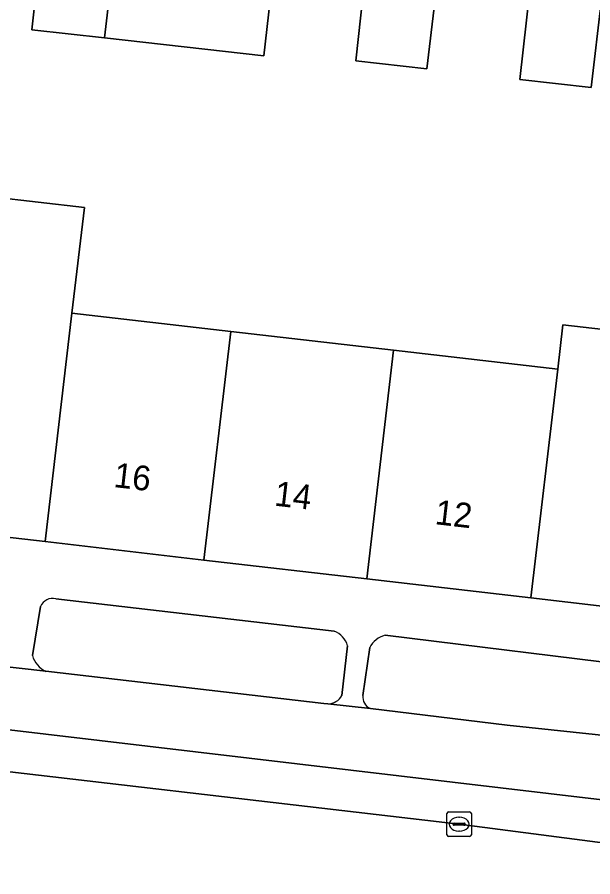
# Model space of a CAD drawing. Extents: x 161692 to 162379, y 380760 to 381678.
# Drawn here: x 162199.65 to 162222.97, y 380911.13 to 380945.92 of the extents above; entities that cross this region are included whole.
import ezdxf

# ---------------------------------------------------------------- set-up
doc = ezdxf.new("R2010")
doc.units = 0
for name, color, linetype in [('IMGEO_Erf', 7, 'Continuous'), ('IMGEO_Groenvoorziening', 7, 'Continuous'), ('IMGEO_Kolk', 7, 'Continuous'), ('IMGEO_Pand', 7, 'Continuous'), ('IMGEO_Pand_nummerreeks', 7, 'Continuous'), ('IMGEO_Parkeervlak_open', 7, 'Continuous'), ('IMGEO_Rijbaan_lokaal_open', 7, 'Continuous'), ('IMGEO_Voetpad_open', 7, 'Continuous')]:
    doc.layers.add(name, color=color, linetype=linetype)

msp = doc.modelspace()

# ---------------------------------------------------------------- linework, layer by layer
at = {"layer": 'IMGEO_Erf'}
for points in [[(162210.092, 380948.286), (162209.651, 380944.358), (162203.188, 380945.084), (162200.242, 380945.415), (162200.683, 380949.343)], [(162216.679, 380947.468), (162216.249, 380943.827), (162213.366, 380944.151), (162213.784, 380947.871)], [(162223.324, 380946.659), (162222.904, 380943.079), (162220.018, 380943.404), (162220.423, 380947.012)], [(162196.729, 380938.872), (162202.378, 380938.225), (162201.872, 380933.936), (162208.311, 380933.198), (162214.905, 380932.442), (162221.551, 380931.68), (162221.756, 380933.47), (162227.997, 380932.755)]]:
    msp.add_lwpolyline(points, dxfattribs=at)
at = {"layer": 'IMGEO_Groenvoorziening'}
for points in [[(162212.489, 380921.068), (162201.22, 380922.384)], [(162200.594, 380922.067), (162200.275, 380920.087)], [(162225.298, 380919.583), (162214.556, 380920.903)], [(162212.812, 380918.469), (162213.037, 380920.478)], [(162213.937, 380920.406), (162213.662, 380918.467)], [(162200.813, 380919.445), (162212.072, 380918.141), (162212.234, 380918.123)], [(162213.961, 380917.936), (162219.5, 380917.26), (162224.855, 380916.697)]]:
    msp.add_lwpolyline(points, dxfattribs=at)
for centre, radius, start, end in [((162201.099, 380921.846), 0.551, 77.3137, 156.4007), ((162212.213, 380920.262), 0.852, 14.6737, 71.099), ((162214.778, 380919.992), 0.938, 103.7154, 153.8071), ((162201.203, 380920.318), 0.957, 194.0021, 245.9243), ((162212.223, 380918.797), 0.674, 270.9057, 330.9051), ((162214.151, 380918.393), 0.495, 171.3558, 247.4109)]:
    msp.add_arc(centre, radius, start, end, dxfattribs=at)
at = {"layer": 'IMGEO_Kolk'}
for p, q in [((162217.132, 380913.757), (162217.984, 380913.757)), ((162217.057, 380912.831), (162217.057, 380913.683)), ((162217.545, 380913.537), (162217.57, 380913.537)), ((162218.058, 380913.683), (162218.058, 380912.831)), ((162217.316, 380913.251), (162217.316, 380913.263)), ((162217.754, 380913.214), (162217.356, 380913.214)), ((162217.359, 380913.3), (162217.757, 380913.3)), ((162217.8, 380913.263), (162217.8, 380913.251)), ((162217.984, 380912.757), (162217.132, 380912.757)), ((162217.568, 380912.977), (162217.543, 380912.977))]:
    msp.add_line(p, q, dxfattribs=at)
for points in [[(162217.132, 380913.757), (162217.984, 380913.757)], [(162217.057, 380912.831), (162217.057, 380913.683)], [(162218.058, 380913.683), (162218.058, 380912.831)], [(162217.984, 380912.757), (162217.132, 380912.757)]]:
    msp.add_lwpolyline(points, dxfattribs=at)
for centre, radius, start, end in [((162217.134, 380913.681), 0.0765, 91.552, 178.448), ((162217.134, 380913.681), 0.0765, 91.552, 178.448), ((162217.982, 380913.681), 0.0765, 1.552, 88.448), ((162217.982, 380913.681), 0.0765, 1.552, 88.448), ((162217.356, 380913.26), 0.0403, 85.8775, 175.7526), ((162217.353, 380913.25), 0.0366, 178.938, 274.7102), ((162217.757, 380913.257), 0.043, 264.8664, 352.4533), ((162217.761, 380913.262), 0.0386, 1.7309, 96.639), ((162217.134, 380912.833), 0.0765, 181.552, 268.448), ((162217.134, 380912.833), 0.0765, 181.552, 268.448), ((162217.982, 380912.833), 0.0765, 271.552, 358.448), ((162217.982, 380912.833), 0.0765, 271.552, 358.448)]:
    msp.add_arc(centre, radius, start, end, dxfattribs=at)
for centre, major_axis, ratio, start_param, end_param in [((162217.544, 380913.257), (-0.387, 0.002), 0.722429, 4.712389, 7.853982), ((162217.569, 380913.257), (-0.39, 0.002), 0.717154, 1.570796, 4.712389)]:
    msp.add_ellipse(centre, major_axis=major_axis, ratio=ratio, start_param=start_param, end_param=end_param, dxfattribs=at)
at = {"layer": 'IMGEO_Pand'}
for points in [[(162203.188, 380945.084), (162203.651, 380949.01), (162200.683, 380949.343), (162200.242, 380945.415)], [(162203.188, 380945.084), (162209.651, 380944.358), (162210.092, 380948.286), (162203.651, 380949.01)], [(162216.679, 380947.468), (162216.688, 380947.545), (162213.784, 380947.871), (162213.366, 380944.151), (162216.249, 380943.827)], [(162223.324, 380946.659), (162223.34, 380946.798), (162220.436, 380947.124), (162220.423, 380947.012), (162220.018, 380943.404), (162222.904, 380943.079)], [(162201.872, 380933.936), (162202.378, 380938.225), (162196.729, 380938.872), (162195.906, 380938.966), (162195.532, 380939.009), (162195.488, 380938.633), (162195.419, 380938.052), (162195.026, 380934.72), (162193.937, 380925.486), (162200.781, 380924.694)], [(162201.872, 380933.936), (162200.781, 380924.694), (162207.219, 380923.949), (162208.311, 380933.198)], [(162227.997, 380932.755), (162221.756, 380933.47), (162221.551, 380931.68), (162220.458, 380922.418), (162226.693, 380921.696)], [(162213.812, 380923.186), (162214.905, 380932.442), (162208.311, 380933.198), (162207.219, 380923.949)], [(162220.458, 380922.418), (162221.551, 380931.68), (162214.905, 380932.442), (162213.812, 380923.186)]]:
    msp.add_lwpolyline(points, close=True, dxfattribs=at)
at = {"layer": 'IMGEO_Parkeervlak_open'}
for points in [[(162247.804, 380913.155), (162247.621, 380914.14), (162246.189, 380913.913), (162242.624, 380913.349), (162241.292, 380913.209), (162238.109, 380913.042), (162236.135, 380912.951), (162233.539, 380913.036), (162176.321, 380919.783)], [(162175.911, 380918.063), (162194.36, 380915.961), (162217.557, 380913.256), (162231.163, 380911.496), (162234.33, 380911.127)]]:
    msp.add_lwpolyline(points, dxfattribs=at)
at = {"layer": 'IMGEO_Rijbaan_lokaal_open'}
msp.add_lwpolyline([(162234.33, 380911.127), (162231.163, 380911.496), (162217.557, 380913.256), (162194.36, 380915.961)], dxfattribs=at)
at = {"layer": 'IMGEO_Voetpad_open'}
for points in [[(162246.079, 380919.46), (162239.67, 380920.198), (162233.283, 380920.934), (162232.951, 380920.972), (162226.693, 380921.696), (162220.458, 380922.418), (162213.812, 380923.186), (162207.219, 380923.949), (162200.781, 380924.694), (162193.937, 380925.486), (162187.797, 380926.197), (162180.993, 380926.984), (162174.757, 380927.705), (162168.21, 380928.463), (162168.105, 380928.475), (162161.646, 380929.214), (162155.105, 380929.962), (162148.655, 380930.7), (162144.778, 380931.153)], [(162200.813, 380919.445), (162198.762, 380919.679), (162187.648, 380920.991), (162185.902, 380921.167), (162185.669, 380921.214), (162174.637, 380922.44), (162172.806, 380922.582), (162172.549, 380922.602), (162160.992, 380923.909), (162159.272, 380924.264), (162153.979, 380924.897), (162153.157, 380924.996), (162141.863, 380926.228), (162138.143, 380926.533), (162138.047, 380925.435)], [(162201.22, 380922.384), (162212.489, 380921.068)], [(162200.275, 380920.087), (162200.594, 380922.067)], [(162214.556, 380920.903), (162225.298, 380919.583)], [(162213.037, 380920.478), (162212.812, 380918.469)], [(162213.662, 380918.467), (162213.937, 380920.406)], [(162176.171, 380918.467), (162176.321, 380919.783), (162233.539, 380913.036), (162236.135, 380912.951), (162238.109, 380913.042), (162241.292, 380913.209), (162242.624, 380913.349), (162246.189, 380913.913), (162247.621, 380914.14), (162247.804, 380913.155)], [(162198.762, 380919.679), (162200.813, 380919.445)], [(162238.13, 380915.475), (162234.191, 380915.527), (162226.845, 380916.402), (162224.992, 380916.663), (162224.855, 380916.697), (162219.5, 380917.26), (162213.961, 380917.936), (162212.234, 380918.123), (162212.072, 380918.141), (162200.813, 380919.445)], [(162212.234, 380918.123), (162213.961, 380917.936)]]:
    msp.add_lwpolyline(points, dxfattribs=at)
for centre, radius, start, end in [((162201.099, 380921.846), 0.551, 77.3137, 156.4007), ((162212.213, 380920.262), 0.852, 14.6737, 71.099), ((162214.778, 380919.992), 0.938, 103.7154, 153.8071), ((162201.203, 380920.318), 0.957, 194.0021, 245.9243), ((162212.223, 380918.797), 0.674, 270.9057, 330.9051), ((162214.151, 380918.393), 0.495, 171.3558, 247.4109)]:
    msp.add_arc(centre, radius, start, end, dxfattribs=at)

# ---------------------------------------------------------------- texts
at = {"layer": 'IMGEO_Pand_nummerreeks'}
for s, p in [('16', (162203.532, 380926.907)), ('14', (162210.041, 380926.156)), ('12', (162216.546, 380925.405))]:
    msp.add_text(s, height=1, rotation=353.4197, dxfattribs=at).set_placement(p)

doc.saveas('drawing.dxf')
